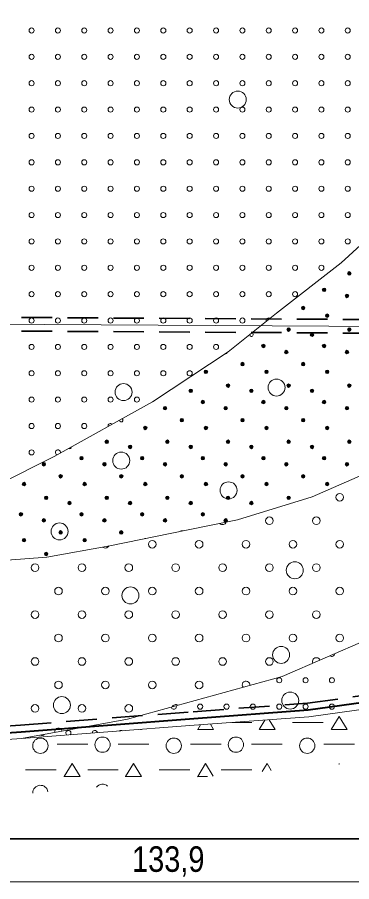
# Model space of a CAD drawing. Extents: x 640104 to 640970, y 6442278 to 6442689.
# Drawn here: x 640319 to 640358.3, y 6442488 to 6442589.6 of the extents above; entities that cross this region are included whole.
import ezdxf
from ezdxf.enums import TextEntityAlignment as Align

# ---------------------------------------------------------------- set-up
doc = ezdxf.new("R2010")
doc.units = 0
doc.header["$LTSCALE"] = 1.2
doc.linetypes.add('MEDIUM_DASHED', pattern=[4.5, 3, -1.5])
for name, color, linetype, lineweight in [('30', 7, 'Continuous', 13), ('31', 7, 'Continuous', 13), ('34', 7, 'Continuous', 25), ('35', 7, 'Continuous', 35), ('42', 7, 'Continuous', 13), ('43', 7, 'Continuous', 13), ('44', 7, 'Continuous', 13), ('46', 7, 'Continuous', 13), ('47', 7, 'Continuous', 13)]:
    doc.layers.add(name, color=color, linetype=linetype, lineweight=lineweight)

msp = doc.modelspace()

# ---------------------------------------------------------------- hatches: boundary and pattern name
at = {"layer": '44'}
for points in [[(640358.237, 6442559.509, 1), (640357.817, 6442559.509, 1)], [(640355.271, 6442557.581, 1), (640354.851, 6442557.581, 1)], [(640357.963, 6442556.866, 1), (640357.543, 6442556.866, 1)], [(640352.808, 6442555.447, 1), (640352.388, 6442555.447, 1)], [(640355.635, 6442554.539, 1), (640355.215, 6442554.539, 1)], [(640351.104, 6442552.913, 1), (640350.684, 6442552.913, 1)], [(640358.237, 6442552.913, 1), (640357.817, 6442552.913, 1)], [(640353.852, 6442552.307, 1), (640353.432, 6442552.307, 1)], [(640348.138, 6442550.985, 1), (640347.718, 6442550.985, 1)], [(640355.271, 6442550.985, 1), (640354.851, 6442550.985, 1)], [(640350.83, 6442550.27, 1), (640350.41, 6442550.27, 1)], [(640357.963, 6442550.27, 1), (640357.543, 6442550.27, 1)], [(640345.675, 6442548.851, 1), (640345.255, 6442548.851, 1)], [(640352.808, 6442548.851, 1), (640352.388, 6442548.851, 1)], [(640341.369, 6442547.943, 1), (640340.949, 6442547.943, 1)], [(640348.502, 6442547.943, 1), (640348.082, 6442547.943, 1)], [(640355.635, 6442547.943, 1), (640355.215, 6442547.943, 1)], [(640339.586, 6442545.711, 1), (640339.166, 6442545.711, 1)], [(640343.971, 6442546.317, 1), (640343.551, 6442546.317, 1)], [(640346.719, 6442545.711, 1), (640346.299, 6442545.711, 1)], [(640351.104, 6442546.317, 1), (640350.684, 6442546.317, 1)], [(640353.852, 6442545.711, 1), (640353.432, 6442545.711, 1)], [(640358.237, 6442546.317, 1), (640357.817, 6442546.317, 1)], [(640341.005, 6442544.389, 1), (640340.585, 6442544.389, 1)], [(640348.138, 6442544.389, 1), (640347.718, 6442544.389, 1)], [(640355.271, 6442544.389, 1), (640354.851, 6442544.389, 1)], [(640336.564, 6442543.674, 1), (640336.144, 6442543.674, 1)], [(640343.697, 6442543.674, 1), (640343.277, 6442543.674, 1)], [(640350.83, 6442543.674, 1), (640350.41, 6442543.674, 1)], [(640357.963, 6442543.674, 1), (640357.543, 6442543.674, 1)], [(640334.236, 6442541.347, 1), (640333.816, 6442541.347, 1)], [(640338.542, 6442542.255, 1), (640338.122, 6442542.255, 1)], [(640341.369, 6442541.347, 1), (640340.949, 6442541.347, 1)], [(640345.675, 6442542.255, 1), (640345.255, 6442542.255, 1)], [(640348.502, 6442541.347, 1), (640348.082, 6442541.347, 1)], [(640352.808, 6442542.255, 1), (640352.388, 6442542.255, 1)], [(640355.635, 6442541.347, 1), (640355.215, 6442541.347, 1)], [(640329.705, 6442539.721, 1), (640329.285, 6442539.721, 1)], [(640336.838, 6442539.721, 1), (640336.418, 6442539.721, 1)], [(640343.971, 6442539.721, 1), (640343.551, 6442539.721, 1)], [(640351.104, 6442539.721, 1), (640350.684, 6442539.721, 1)], [(640358.237, 6442539.721, 1), (640357.817, 6442539.721, 1)], [(640332.453, 6442539.115, 1), (640332.033, 6442539.115, 1)], [(640339.586, 6442539.115, 1), (640339.166, 6442539.115, 1)], [(640346.719, 6442539.115, 1), (640346.299, 6442539.115, 1)], [(640353.852, 6442539.115, 1), (640353.432, 6442539.115, 1)], [(640326.739, 6442537.793, 1), (640326.319, 6442537.793, 1)], [(640333.872, 6442537.793, 1), (640333.452, 6442537.793, 1)], [(640341.005, 6442537.793, 1), (640340.585, 6442537.793, 1)], [(640348.138, 6442537.793, 1), (640347.718, 6442537.793, 1)], [(640355.271, 6442537.793, 1), (640354.851, 6442537.793, 1)], [(640322.298, 6442537.078, 1), (640321.878, 6442537.078, 1)], [(640329.431, 6442537.078, 1), (640329.011, 6442537.078, 1)], [(640336.564, 6442537.078, 1), (640336.144, 6442537.078, 1)], [(640343.697, 6442537.078, 1), (640343.277, 6442537.078, 1)], [(640350.83, 6442537.078, 1), (640350.41, 6442537.078, 1)], [(640357.963, 6442537.078, 1), (640357.543, 6442537.078, 1)], [(640324.276, 6442535.659, 1), (640323.856, 6442535.659, 1)], [(640331.409, 6442535.659, 1), (640330.989, 6442535.659, 1)], [(640338.542, 6442535.659, 1), (640338.122, 6442535.659, 1)], [(640345.675, 6442535.659, 1), (640345.255, 6442535.659, 1)], [(640352.808, 6442535.659, 1), (640352.388, 6442535.659, 1)], [(640319.97, 6442534.751, 1), (640319.55, 6442534.751, 1)], [(640327.103, 6442534.751, 1), (640326.683, 6442534.751, 1)], [(640334.236, 6442534.751, 1), (640333.816, 6442534.751, 1)], [(640341.369, 6442534.751, 1), (640340.949, 6442534.751, 1)], [(640348.502, 6442534.751, 1), (640348.082, 6442534.751, 1)], [(640355.635, 6442534.751, 1), (640355.215, 6442534.751, 1)], [(640322.572, 6442533.125, 1), (640322.152, 6442533.125, 1)], [(640325.32, 6442532.519, 1), (640324.9, 6442532.519, 1)], [(640329.705, 6442533.125, 1), (640329.285, 6442533.125, 1)], [(640332.453, 6442532.519, 1), (640332.033, 6442532.519, 1)], [(640336.838, 6442533.125, 1), (640336.418, 6442533.125, 1)], [(640339.586, 6442532.519, 1), (640339.166, 6442532.519, 1)], [(640343.971, 6442533.125, 1), (640343.551, 6442533.125, 1)], [(640346.719, 6442532.519, 1), (640346.299, 6442532.519, 1)], [(640351.104, 6442533.125, 1), (640350.684, 6442533.125, 1)], [(640319.606, 6442531.197, 1), (640319.186, 6442531.197, 1)], [(640326.739, 6442531.197, 1), (640326.319, 6442531.197, 1)], [(640333.872, 6442531.197, 1), (640333.452, 6442531.197, 1)], [(640341.005, 6442531.197, 1), (640340.585, 6442531.197, 1)], [(640322.298, 6442530.482, 1), (640321.878, 6442530.482, 1)], [(640329.431, 6442530.482, 1), (640329.011, 6442530.482, 1)], [(640336.564, 6442530.482, 1), (640336.144, 6442530.482, 1)], [(640343.697, 6442530.482, 1), (640343.277, 6442530.482, 1)], [(640319.97, 6442528.155, 1), (640319.55, 6442528.155, 1)], [(640324.276, 6442529.063, 1), (640323.856, 6442529.063, 1)], [(640327.103, 6442528.155, 1), (640326.683, 6442528.155, 1)], [(640331.409, 6442529.063, 1), (640330.989, 6442529.063, 1)], [(640322.572, 6442526.529, 1), (640322.152, 6442526.529, 1)]]:
    msp.add_hatch(color=256, dxfattribs=at).paths.add_polyline_path(points)

# ---------------------------------------------------------------- linework, layer by layer
at = {"layer": '31'}
for p, q in [((640107.01, 6442493.07), (640418.42, 6442493.07)), ((640107.01, 6442493), (640418.42, 6442493)), ((640107.01, 6442488), (640418.42, 6442488))]:
    msp.add_line(p, q, dxfattribs=at)
for points in [[(640283.68, 6442523.66), (640285.43, 6442524.03), (640297.52, 6442526.8), (640310.03, 6442531.34), (640323.29, 6442537.98), (640334.86, 6442544.42), (640343.76, 6442550.3), (640349.45, 6442554.85), (640357.08, 6442560.74), (640362.52, 6442565.74), (640369.51, 6442571.79), (640374.98, 6442577.56), (640379.02, 6442582.52), (640385.32, 6442590.78), (640390.41, 6442598.26), (640395.12, 6442604.77), (640397.49, 6442607.37), (640400.85, 6442610.03)], [(640224.72, 6442522.23), (640247.13, 6442522.05), (640267.13, 6442522.88), (640278.78, 6442523.38), (640298.96, 6442524.54), (640307.35, 6442525), (640322.43, 6442526.17), (640329.85, 6442527.49), (640338.89, 6442529.33), (640344.87, 6442530.55), (640353.66, 6442533.23), (640361.47, 6442536.65), (640368.18, 6442539.82), (640375.75, 6442544.7), (640385.64, 6442551.91), (640392.23, 6442556.06), (640395.16, 6442557.52), (640398.21, 6442558.74), (640401.26, 6442559.84), (640404.41, 6442560.91), (640412.75, 6442561.86), (640417.91, 6442562.22), (640418.42, 6442562.2)], [(640398.21, 6442558.74), (640394.67, 6442556.18), (640391.86, 6442552.76), (640389.56, 6442549.24), (640387.72, 6442546.31), (640384.42, 6442540.19), (640380.75, 6442534.21), (640376.6, 6442529.2), (640371.48, 6442524.44), (640364.4, 6442518.71), (640360.25, 6442516.51), (640350.12, 6442512.12), (640331.93, 6442507.11), (640319.46, 6442504.83)], [(640136.43, 6442546.57), (640165.21, 6442545.08), (640170.39, 6442544.98), (640270.85, 6442502.92), (640281.03, 6442503.04), (640287.95, 6442503.15), (640297.33, 6442503.37), (640306.38, 6442503.93), (640319.46, 6442504.83), (640339.78, 6442506.39), (640353.27, 6442507.39), (640379.6, 6442511.07), (640396.05, 6442513.09), (640404.66, 6442514), (640412.22, 6442514.76), (640418.42, 6442515.39)]]:
    msp.add_lwpolyline(points, dxfattribs=at)
at = {"layer": '34', "lineweight": 13}
msp.add_lwpolyline([(640136.43, 6442567), (640170.34, 6442565), (640269.82, 6442552.96), (640308.67, 6442553.6), (640395.86, 6442553.07), (640412.35, 6442552.95), (640418.42, 6442552.96)], dxfattribs=at)
at = {"layer": '35', "linetype": 'MEDIUM_DASHED'}
for points in [[(640171.96, 6442565.61), (640269.86, 6442553.76), (640308.67, 6442554.4), (640395.87, 6442553.87), (640403.06, 6442553.81)], [(640171.96, 6442564), (640269.77, 6442552.16), (640308.67, 6442552.8), (640395.86, 6442552.27), (640403.06, 6442552.21)], [(640171.96, 6442546.06), (640271.16, 6442504.53), (640281.01, 6442504.64), (640287.92, 6442504.75), (640297.26, 6442504.97), (640306.27, 6442505.53), (640319.35, 6442506.42), (640339.66, 6442507.99), (640353.1, 6442508.98), (640379.39, 6442512.65), (640395.87, 6442514.68), (640403.06, 6442515.44)]]:
    msp.add_lwpolyline(points, dxfattribs=at)
at = {"layer": '35', "lineweight": 40}
msp.add_lwpolyline([(640171.16, 6442545.53), (640271, 6442503.73), (640281.02, 6442503.84), (640287.94, 6442503.95), (640297.3, 6442504.17), (640306.32, 6442504.73), (640319.41, 6442505.62), (640339.72, 6442507.19), (640353.18, 6442508.19), (640379.49, 6442511.86), (640395.96, 6442513.88), (640403.86, 6442514.72)], dxfattribs=at)
at = {"layer": '42'}
for centre in [(640356.909, 6442533.193), (640348.636, 6442530.435), (640354.152, 6442530.435), (640334.848, 6442527.678), (640340.363, 6442527.678), (640345.879, 6442527.678), (640351.394, 6442527.678), (640356.909, 6442527.678), (640321.059, 6442524.92), (640326.575, 6442524.92), (640332.09, 6442524.92), (640337.605, 6442524.92), (640343.121, 6442524.92), (640348.636, 6442524.92), (640354.152, 6442524.92), (640323.817, 6442522.162), (640329.332, 6442522.162), (640334.848, 6442522.162), (640340.363, 6442522.162), (640345.879, 6442522.162), (640351.394, 6442522.162), (640356.909, 6442522.162), (640321.059, 6442519.404), (640326.575, 6442519.404), (640332.09, 6442519.404), (640337.605, 6442519.404), (640343.121, 6442519.404), (640348.636, 6442519.404), (640354.152, 6442519.404), (640323.817, 6442516.647), (640329.332, 6442516.647), (640334.848, 6442516.647), (640340.363, 6442516.647), (640345.879, 6442516.647), (640351.394, 6442516.647), (640356.909, 6442516.647), (640321.059, 6442513.889), (640326.575, 6442513.889), (640332.09, 6442513.889), (640337.605, 6442513.889), (640343.121, 6442513.889), (640348.636, 6442513.889), (640323.817, 6442511.131), (640329.332, 6442511.131), (640334.848, 6442511.131), (640340.363, 6442511.131), (640321.059, 6442508.374), (640326.575, 6442508.374), (640332.09, 6442508.374)]:
    msp.add_circle(centre, 0.45, dxfattribs=at)
for centre, start, end in [((640343.121, 6442530.435), 223.88919, 339.18005), ((640329.332, 6442527.678), 227.33667, 332.93554), ((640354.152, 6442513.889), 20.68483, 206.21129), ((640345.879, 6442511.131), 352.39769, 218.37268), ((640337.605, 6442508.374), 55.21496, 155.55542), ((640323.817, 6442505.616), 11.45528, 189.30829)]:
    msp.add_arc(centre, 0.45, start, end, dxfattribs=at)
at = {"layer": '43'}
for centre in [(640320.649, 6442588.073), (640323.749, 6442588.073), (640326.849, 6442588.073), (640329.949, 6442588.073), (640333.049, 6442588.073), (640336.149, 6442588.073), (640339.249, 6442588.073), (640342.349, 6442588.073), (640345.449, 6442588.073), (640348.549, 6442588.073), (640351.649, 6442588.073), (640354.749, 6442588.073), (640357.849, 6442588.073), (640320.649, 6442584.973), (640323.749, 6442584.973), (640326.849, 6442584.973), (640329.949, 6442584.973), (640333.049, 6442584.973), (640336.149, 6442584.973), (640339.249, 6442584.973), (640342.349, 6442584.973), (640345.449, 6442584.973), (640348.549, 6442584.973), (640351.649, 6442584.973), (640354.749, 6442584.973), (640357.849, 6442584.973), (640320.649, 6442581.873), (640323.749, 6442581.873), (640326.849, 6442581.873), (640329.949, 6442581.873), (640333.049, 6442581.873), (640336.149, 6442581.873), (640339.249, 6442581.873), (640342.349, 6442581.873), (640345.449, 6442581.873), (640348.549, 6442581.873), (640351.649, 6442581.873), (640354.749, 6442581.873), (640357.849, 6442581.873), (640320.649, 6442578.773), (640323.749, 6442578.773), (640326.849, 6442578.773), (640329.949, 6442578.773), (640333.049, 6442578.773), (640336.149, 6442578.773), (640339.249, 6442578.773), (640342.349, 6442578.773), (640345.449, 6442578.773), (640348.549, 6442578.773), (640351.649, 6442578.773), (640354.749, 6442578.773), (640357.849, 6442578.773), (640320.649, 6442575.673), (640323.749, 6442575.673), (640326.849, 6442575.673), (640329.949, 6442575.673), (640333.049, 6442575.673), (640336.149, 6442575.673), (640339.249, 6442575.673), (640342.349, 6442575.673), (640345.449, 6442575.673), (640348.549, 6442575.673), (640351.649, 6442575.673), (640354.749, 6442575.673), (640357.849, 6442575.673), (640320.649, 6442572.573), (640323.749, 6442572.573), (640326.849, 6442572.573), (640329.949, 6442572.573), (640333.049, 6442572.573), (640336.149, 6442572.573), (640339.249, 6442572.573), (640342.349, 6442572.573), (640345.449, 6442572.573), (640348.549, 6442572.573), (640351.649, 6442572.573), (640354.749, 6442572.573), (640357.849, 6442572.573), (640320.649, 6442569.473), (640323.749, 6442569.473), (640326.849, 6442569.473), (640329.949, 6442569.473), (640333.049, 6442569.473), (640336.149, 6442569.473), (640339.249, 6442569.473), (640342.349, 6442569.473), (640345.449, 6442569.473), (640348.549, 6442569.473), (640351.649, 6442569.473), (640354.749, 6442569.473), (640357.849, 6442569.473), (640320.649, 6442566.373), (640323.749, 6442566.373), (640326.849, 6442566.373), (640329.949, 6442566.373), (640333.049, 6442566.373), (640336.149, 6442566.373), (640339.249, 6442566.373), (640342.349, 6442566.373), (640345.449, 6442566.373), (640348.549, 6442566.373), (640351.649, 6442566.373), (640354.749, 6442566.373), (640357.849, 6442566.373), (640320.649, 6442563.273), (640323.749, 6442563.273), (640326.849, 6442563.273), (640329.949, 6442563.273), (640333.049, 6442563.273), (640336.149, 6442563.273), (640339.249, 6442563.273), (640342.349, 6442563.273), (640345.449, 6442563.273), (640348.549, 6442563.273), (640351.649, 6442563.273), (640354.749, 6442563.273), (640357.849, 6442563.273), (640320.649, 6442560.173), (640323.749, 6442560.173), (640326.849, 6442560.173), (640329.949, 6442560.173), (640333.049, 6442560.173), (640336.149, 6442560.173), (640339.249, 6442560.173), (640342.349, 6442560.173), (640345.449, 6442560.173), (640348.549, 6442560.173), (640351.649, 6442560.173), (640354.749, 6442560.173), (640320.649, 6442557.073), (640323.749, 6442557.073), (640326.849, 6442557.073), (640329.949, 6442557.073), (640333.049, 6442557.073), (640336.149, 6442557.073), (640339.249, 6442557.073), (640342.349, 6442557.073), (640345.449, 6442557.073), (640348.549, 6442557.073), (640351.649, 6442557.073), (640320.649, 6442553.973), (640323.749, 6442553.973), (640326.849, 6442553.973), (640329.949, 6442553.973), (640333.049, 6442553.973), (640336.149, 6442553.973), (640339.249, 6442553.973), (640342.349, 6442553.973), (640345.449, 6442553.973), (640320.649, 6442550.873), (640323.749, 6442550.873), (640326.849, 6442550.873), (640329.949, 6442550.873), (640333.049, 6442550.873), (640336.149, 6442550.873), (640339.249, 6442550.873), (640342.349, 6442550.873), (640320.649, 6442547.773), (640323.749, 6442547.773), (640326.849, 6442547.773), (640329.949, 6442547.773), (640333.049, 6442547.773), (640336.149, 6442547.773), (640339.249, 6442547.773), (640320.649, 6442544.673), (640323.749, 6442544.673), (640326.849, 6442544.673), (640329.949, 6442544.673), (640333.049, 6442544.673), (640320.649, 6442541.573), (640323.749, 6442541.573), (640326.849, 6442541.573), (640320.649, 6442538.473), (640349.785, 6442511.68), (640352.885, 6442511.68), (640355.985, 6442511.68), (640340.485, 6442508.58), (640343.585, 6442508.58), (640346.685, 6442508.58), (640349.785, 6442508.58), (640352.885, 6442508.58), (640355.985, 6442508.58)]:
    msp.add_circle(centre, 0.3, dxfattribs=at)
for centre, start, end in [((640348.549, 6442553.973), 62.02003, 195.29959), ((640329.949, 6442541.573), 48.48614, 189.78244), ((640323.749, 6442538.473), 344.35331, 253.91528), ((640355.985, 6442514.78), 224.97186, 1.92427), ((640337.385, 6442508.58), 189.58841, 21.18197), ((640321.885, 6442505.48), 233.87067, 326.8929), ((640324.985, 6442505.48), 314.93705, 233.86036), ((640328.085, 6442505.48), 6.26455, 182.53286), ((640331.185, 6442505.48), 59.9963, 128.80111)]:
    msp.add_arc(centre, 0.3, start, end, dxfattribs=at)
at = {"layer": '44'}
for centre in [(640358.027, 6442559.509), (640355.061, 6442557.581), (640357.753, 6442556.866), (640352.598, 6442555.447), (640355.425, 6442554.539), (640350.894, 6442552.913), (640358.027, 6442552.913), (640353.642, 6442552.307), (640347.928, 6442550.985), (640355.061, 6442550.985), (640350.62, 6442550.27), (640357.753, 6442550.27), (640345.465, 6442548.851), (640352.598, 6442548.851), (640341.159, 6442547.943), (640348.292, 6442547.943), (640355.425, 6442547.943), (640339.376, 6442545.711), (640343.761, 6442546.317), (640346.509, 6442545.711), (640350.894, 6442546.317), (640353.642, 6442545.711), (640358.027, 6442546.317), (640340.795, 6442544.389), (640347.928, 6442544.389), (640355.061, 6442544.389), (640336.354, 6442543.674), (640343.487, 6442543.674), (640350.62, 6442543.674), (640357.753, 6442543.674), (640334.026, 6442541.347), (640338.332, 6442542.255), (640341.159, 6442541.347), (640345.465, 6442542.255), (640348.292, 6442541.347), (640352.598, 6442542.255), (640355.425, 6442541.347), (640329.495, 6442539.721), (640336.628, 6442539.721), (640343.761, 6442539.721), (640350.894, 6442539.721), (640358.027, 6442539.721), (640332.243, 6442539.115), (640339.376, 6442539.115), (640346.509, 6442539.115), (640353.642, 6442539.115), (640326.529, 6442537.793), (640333.662, 6442537.793), (640340.795, 6442537.793), (640347.928, 6442537.793), (640355.061, 6442537.793), (640322.088, 6442537.078), (640329.221, 6442537.078), (640336.354, 6442537.078), (640343.487, 6442537.078), (640350.62, 6442537.078), (640357.753, 6442537.078), (640324.066, 6442535.659), (640331.199, 6442535.659), (640338.332, 6442535.659), (640345.465, 6442535.659), (640352.598, 6442535.659), (640319.76, 6442534.751), (640326.893, 6442534.751), (640334.026, 6442534.751), (640341.159, 6442534.751), (640348.292, 6442534.751), (640355.425, 6442534.751), (640322.362, 6442533.125), (640325.11, 6442532.519), (640329.495, 6442533.125), (640332.243, 6442532.519), (640336.628, 6442533.125), (640339.376, 6442532.519), (640343.761, 6442533.125), (640346.509, 6442532.519), (640350.894, 6442533.125), (640319.396, 6442531.197), (640326.529, 6442531.197), (640333.662, 6442531.197), (640340.795, 6442531.197), (640322.088, 6442530.482), (640329.221, 6442530.482), (640336.354, 6442530.482), (640343.487, 6442530.482), (640319.76, 6442528.155), (640324.066, 6442529.063), (640326.893, 6442528.155), (640331.199, 6442529.063), (640322.362, 6442526.529)]:
    msp.add_circle(centre, 0.21, dxfattribs=at)
for centre, start, end in [((640346.509, 6442552.307), 175.01819, 82.30142), ((640343.487, 6442550.27), 251.41376, 355.40189), ((640331.199, 6442542.255), 176.86695, 61.40164), ((640325.11, 6442539.115), 240.74599, 357.5226), ((640334.026, 6442528.155), 71.46264, 131.45487), ((640338.332, 6442529.063), 55.88547, 147.03203)]:
    msp.add_arc(centre, 0.21, start, end, dxfattribs=at)
at = {"layer": '46'}
for p, q in [((640346.55, 6442506.72), (640344.19, 6442506.72)), ((640354.94, 6442506.72), (640351.34, 6442506.72)), ((640327.25, 6442504.16), (640323.65, 6442504.16)), ((640334.45, 6442504.16), (640330.85, 6442504.16)), ((640342.95, 6442504.16), (640339.35, 6442504.16)), ((640350.14, 6442504.16), (640346.54, 6442504.16)), ((640358.64, 6442504.16), (640355.04, 6442504.16)), ((640323.55, 6442501.17), (640319.95, 6442501.17)), ((640330.85, 6442501.16), (640327.25, 6442501.16)), ((640339.25, 6442501.17), (640335.65, 6442501.17)), ((640346.55, 6442501.16), (640342.95, 6442501.16)), ((640341.36, 6442500.35), (640340.26, 6442500.36))]:
    msp.add_line(p, q, dxfattribs=at)
for points in [[(640347.41, 6442505.89), (640347.41, 6442505.91), (640348.09, 6442507.01)], [(640348.6, 6442507.05), (640349.29, 6442505.9), (640347.49, 6442505.91)], [(640355.88, 6442505.89), (640355.88, 6442505.91), (640356.83, 6442507.44), (640357.76, 6442505.9), (640355.96, 6442505.91)], [(640340.18, 6442505.89), (640340.19, 6442505.91), (640340.52, 6442506.44)], [(640341.69, 6442506.53), (640342.06, 6442505.9), (640340.26, 6442505.91)], [(640333.59, 6442505.91), (640333.59, 6442505.9), (640333.47, 6442505.9)], [(640324.49, 6442500.34), (640324.49, 6442500.36), (640325.44, 6442501.89), (640326.37, 6442500.35), (640324.57, 6442500.36)], [(640331.71, 6442500.34), (640331.71, 6442500.36), (640332.66, 6442501.89), (640333.59, 6442500.35), (640331.79, 6442500.36)], [(640340.18, 6442500.34), (640340.19, 6442500.36), (640341.13, 6442501.89), (640342.02, 6442500.42)], [(640347.78, 6442500.97), (640348.36, 6442501.89), (640348.85, 6442501.07)], [(640356.79, 6442501.83), (640356.83, 6442501.89), (640356.86, 6442501.83)]]:
    msp.add_lwpolyline(points, dxfattribs=at)
for centre in [(640328.998, 6442504.112), (640344.693, 6442504.112), (640321.685, 6442503.99), (640337.38, 6442503.99), (640353.076, 6442503.99)]:
    msp.add_circle(centre, 0.9, dxfattribs=at)
for centre, start, end in [((640321.685, 6442498.435), 7.83481, 180.4841), ((640328.998, 6442498.557), 48.24979, 142.66779)]:
    msp.add_arc(centre, 0.9, start, end, dxfattribs=at)
at = {"layer": '47'}
for centre in [(640344.903, 6442579.945), (640349.469, 6442546.098), (640331.471, 6442545.561), (640331.202, 6442537.502), (640343.828, 6442534.01), (640323.949, 6442529.174), (640351.618, 6442524.608), (640332.277, 6442521.653), (640350.006, 6442514.668), (640351.081, 6442509.296), (640324.218, 6442508.758)]:
    msp.add_circle(centre, 1, dxfattribs=at)

# ---------------------------------------------------------------- texts
at = {"layer": '30', "width": 0.85}
msp.add_text('133,9', height=3, dxfattribs=at).set_placement((640336.73, 6442489.16), align=Align.CENTER)

doc.saveas('drawing.dxf')
